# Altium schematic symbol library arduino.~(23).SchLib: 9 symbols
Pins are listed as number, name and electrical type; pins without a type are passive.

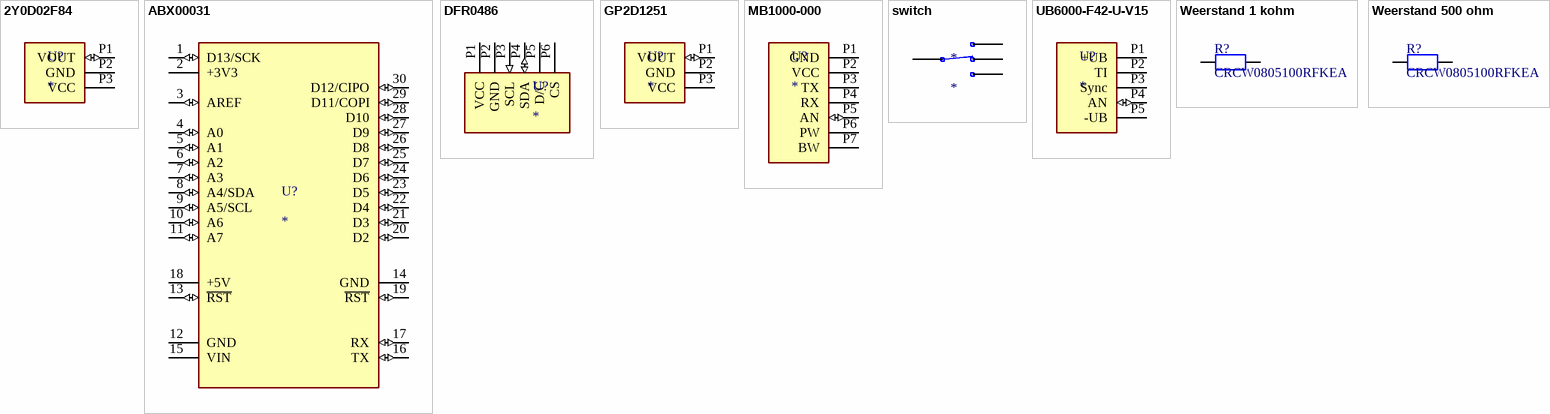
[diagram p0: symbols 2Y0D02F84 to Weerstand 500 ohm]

## 2Y0D02F84
designator U?
SENSOR OPTICAL ANALOG; MP: GP2D120; MF: Sharp
footprint GP2DXX
pins: P1 VOUT (io), P2 GND (power), P3 VCC (power)

## ABX00031
designator U?
Arduino Nano 33 BLE; MP: ABX00030
footprint MODULE_ABX00030
pins: 1 D13/SCK (io), 2 +3V3 (power), 3 AREF (io), 4 A0 (io), 5 A1 (io), 6 A2 (io), 7 A3 (io), 8 A4/SDA (io), 9 A5/SCL (io), 10 A6 (io), 11 A7 (io), 12 GND (power), 13 ~{RST} (io), 14 GND (power), 15 VIN (power), 16 TX (io), 17 RX (io), 18 +5V (power), 19 ~{RST} (io), 20 D2 (io), 21 D3 (io), 22 D4 (io), 23 D5 (io), 24 D6 (io), 25 D7 (io), 26 D8 (io), 27 D9 (io), 28 D10 (io), 29 D11/COPI (io), 30 D12/CIPO (io)

## DFR0486
designator U?
0.96" 128x64 OLED(V1.0) display DFROBOT; MP: GP2D120; MF: Sharp
footprint GP2DXX
pins: P1 VCC (power), P2 GND (power), P3 SCL (in), P4 SDA (io), P5 D/C (oc), P6 CS (oc)

## GP2D1251
designator U?
SENSOR OPTICAL ANALOG; MP: GP2D120; MF: Sharp
footprint GP2DXX
pins: P1 VOUT (io), P2 GND (power), P3 VCC (power)

## MB1000-000
designator U?
Analog ultrasonic sensor; MP: GP2D120; MF: Sharp
footprint GP2DXX
pins: P1 GND (power), P2 VCC (power), P3 TX (oc), P4 RX (oc), P5 AN (io), P6 PW (oe), P7 BW (oe)

## switch
designator *
pins: ?1 (power), ?2 (power), ?3 (power), ?4 (power)

## UB6000-F42-U-V15
designator U?
Ultrasonic sensor; MP: GP2D120; MF: Sharp
footprint GP2DXX
pins: P1 +UB (power), P2 TI (oc), P3 Sync (oc), P4 AN (io), P5 -UB (power)

## Weerstand 1 kohm
designator R?, comment CRCW0805100RFKEA
Manufacturer: Vishay Dale
footprint Weerstand 1M ohm
pins: 1, 2
1 alternate drawing of the same symbol

## Weerstand 500 ohm
designator R?, comment CRCW0805100RFKEA
Manufacturer: Vishay Dale
footprint Weerstand 1M ohm
pins: 1, 2
1 alternate drawing of the same symbol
